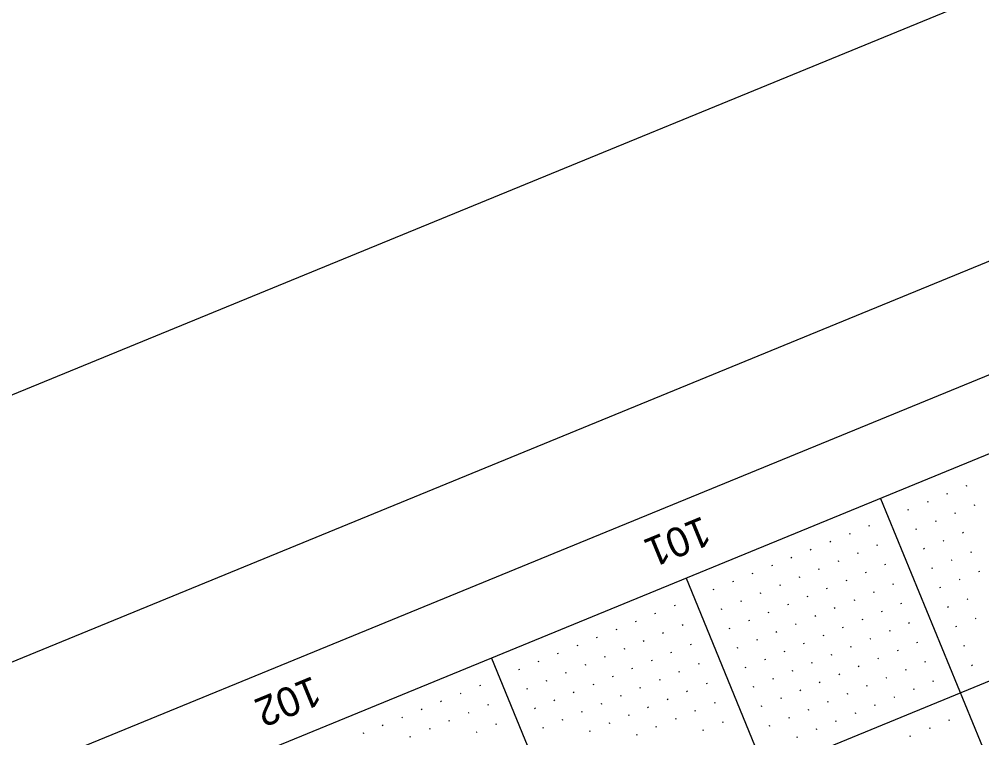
# Model space of a CAD drawing. Extents: x 2148770 to 2150891, y 142633 to 144465.
# Drawn here: x 2149281.6 to 2149510.3, y 143871.3 to 144042.2 of the extents above; entities that cross this region are included whole.
import ezdxf

# ---------------------------------------------------------------- set-up
doc = ezdxf.new("R2010")
doc.units = 0
for name, color, linetype in [('SHT_Plan_Profile_Sheet_Sta_Txt', 7, 'Continuous'), ('SHT_Plot_Shape_Full', 7, 'Continuous'), ('SHT_Plot_Shape_Half', 7, 'Continuous'), ('SHT_Profile_Grid_Major', 7, 'Continuous'), ('SHT_Profile_Grid_Minor', 7, 'Continuous'), ('SHT_Sheet_Border', 7, 'Continuous')]:
    doc.layers.add(name, color=color, linetype=linetype)

msp = doc.modelspace()

# ---------------------------------------------------------------- linework, layer by layer
at = {"layer": 'SHT_Plot_Shape_Full'}
msp.add_lwpolyline([(2150890.55, 143316.95), (2149225.42, 142633.31), (2148769.66, 143743.39), (2150434.78, 144427.04)], close=True, dxfattribs=at)
at = {"layer": 'SHT_Plot_Shape_Half'}
msp.add_lwpolyline([(2150799.14, 143324.02), (2149226.52, 142678.36), (2148808.74, 143695.93), (2150381.36, 144341.59)], close=True, dxfattribs=at)
at = {"layer": 'SHT_Profile_Grid_Major'}
for p, q in [((2150326.3, 144218.99), (2148869.31, 143620.81)), ((2149486.31, 143928.17), (2149676.21, 143465.64)), ((2149440.05, 143909.18), (2149629.95, 143446.65)), ((2149393.8, 143890.19), (2149583.7, 143427.66))]:
    msp.add_line(p, q, dxfattribs=at)
at = {"layer": 'SHT_Profile_Grid_Minor'}
for p, q in [((2149506.82, 143931.19), (2149506.59, 143931.1)), ((2149502.2, 143929.29), (2149501.97, 143929.2)), ((2149497.57, 143927.39), (2149497.34, 143927.3)), ((2149508.72, 143926.57), (2149508.49, 143926.47)), ((2149492.95, 143925.49), (2149492.72, 143925.4)), ((2149504.1, 143924.67), (2149503.87, 143924.57)), ((2149499.47, 143922.77), (2149499.24, 143922.67)), ((2149479.07, 143919.8), (2149478.84, 143919.7)), ((2149483.7, 143921.7), (2149483.46, 143921.6)), ((2149494.85, 143920.87), (2149494.61, 143920.77)), ((2149506, 143920.04), (2149505.76, 143919.95)), ((2149474.45, 143917.9), (2149474.21, 143917.8)), ((2149501.37, 143918.14), (2149501.14, 143918.05)), ((2149469.82, 143916), (2149469.59, 143915.9)), ((2149480.97, 143915.17), (2149480.74, 143915.08)), ((2149485.6, 143917.07), (2149485.36, 143916.98)), ((2149496.75, 143916.24), (2149496.51, 143916.15)), ((2149507.89, 143915.42), (2149507.66, 143915.32)), ((2149465.19, 143914.1), (2149464.96, 143914)), ((2149476.34, 143913.27), (2149476.11, 143913.18)), ((2149503.27, 143913.52), (2149503.04, 143913.42)), ((2149460.57, 143912.2), (2149460.34, 143912.11)), ((2149471.72, 143911.37), (2149471.49, 143911.28)), ((2149482.87, 143910.55), (2149482.64, 143910.45)), ((2149487.49, 143912.44), (2149487.26, 143912.35)), ((2149498.64, 143911.62), (2149498.41, 143911.52)), ((2149509.79, 143910.79), (2149509.56, 143910.7)), ((2149451.32, 143908.4), (2149451.09, 143908.31)), ((2149455.94, 143910.3), (2149455.71, 143910.21)), ((2149467.09, 143909.47), (2149466.86, 143909.38)), ((2149478.24, 143908.65), (2149478.01, 143908.55)), ((2149505.17, 143908.89), (2149504.94, 143908.8)), ((2149446.69, 143906.5), (2149446.46, 143906.41)), ((2149462.47, 143907.58), (2149462.24, 143907.48)), ((2149473.62, 143906.75), (2149473.39, 143906.65)), ((2149484.77, 143905.92), (2149484.54, 143905.83)), ((2149489.39, 143907.82), (2149489.16, 143907.72)), ((2149500.54, 143906.99), (2149500.31, 143906.9)), ((2149453.22, 143903.78), (2149452.99, 143903.68)), ((2149457.84, 143905.68), (2149457.61, 143905.58)), ((2149468.99, 143904.85), (2149468.76, 143904.75)), ((2149480.14, 143904.02), (2149479.91, 143903.93)), ((2149507.07, 143904.27), (2149506.84, 143904.17)), ((2149437.44, 143902.71), (2149437.21, 143902.61)), ((2149448.59, 143901.88), (2149448.36, 143901.78)), ((2149464.37, 143902.95), (2149464.14, 143902.85)), ((2149475.52, 143902.12), (2149475.29, 143902.03)), ((2149486.67, 143901.3), (2149486.44, 143901.2)), ((2149491.29, 143903.19), (2149491.06, 143903.1)), ((2149502.44, 143902.37), (2149502.21, 143902.27)), ((2149432.82, 143900.81), (2149432.59, 143900.71)), ((2149455.12, 143899.15), (2149454.89, 143899.06)), ((2149459.74, 143901.05), (2149459.51, 143900.96)), ((2149470.89, 143900.22), (2149470.66, 143900.13)), ((2149482.04, 143899.4), (2149481.81, 143899.3)), ((2149508.97, 143899.64), (2149508.74, 143899.55)), ((2149423.57, 143897.01), (2149423.34, 143896.91)), ((2149428.19, 143898.91), (2149427.96, 143898.81)), ((2149439.34, 143898.08), (2149439.11, 143897.99)), ((2149450.49, 143897.25), (2149450.26, 143897.16)), ((2149466.27, 143898.32), (2149466.04, 143898.23)), ((2149477.42, 143897.5), (2149477.18, 143897.4)), ((2149493.19, 143898.57), (2149492.96, 143898.47)), ((2149504.34, 143897.74), (2149504.11, 143897.65)), ((2149418.94, 143895.11), (2149418.71, 143895.01)), ((2149434.72, 143896.18), (2149434.49, 143896.09)), ((2149457.02, 143894.53), (2149456.78, 143894.43)), ((2149461.64, 143896.43), (2149461.41, 143896.33)), ((2149472.79, 143895.6), (2149472.56, 143895.5)), ((2149483.94, 143894.77), (2149483.71, 143894.68)), ((2149488.57, 143896.67), (2149488.33, 143896.57)), ((2149414.32, 143893.21), (2149414.08, 143893.12)), ((2149425.47, 143892.38), (2149425.23, 143892.29)), ((2149430.09, 143894.28), (2149429.86, 143894.19)), ((2149441.24, 143893.45), (2149441.01, 143893.36)), ((2149452.39, 143892.63), (2149452.16, 143892.53)), ((2149468.17, 143893.7), (2149467.93, 143893.6)), ((2149479.32, 143892.87), (2149479.08, 143892.78)), ((2149495.09, 143893.94), (2149494.86, 143893.85)), ((2149506.24, 143893.12), (2149506.01, 143893.02)), ((2149409.69, 143891.31), (2149409.46, 143891.22)), ((2149420.84, 143890.48), (2149420.61, 143890.39)), ((2149436.62, 143891.56), (2149436.38, 143891.46)), ((2149458.91, 143889.9), (2149458.68, 143889.81)), ((2149463.54, 143891.8), (2149463.31, 143891.71)), ((2149474.69, 143890.97), (2149474.46, 143890.88)), ((2149485.84, 143890.15), (2149485.61, 143890.05)), ((2149490.46, 143892.04), (2149490.23, 143891.95)), ((2149405.07, 143889.41), (2149404.83, 143889.32)), ((2149416.22, 143888.59), (2149415.98, 143888.49)), ((2149427.36, 143887.76), (2149427.13, 143887.66)), ((2149431.99, 143889.66), (2149431.76, 143889.56)), ((2149443.14, 143888.83), (2149442.91, 143888.73)), ((2149454.29, 143888), (2149454.06, 143887.91)), ((2149470.06, 143889.07), (2149469.83, 143888.98)), ((2149481.21, 143888.25), (2149480.98, 143888.15)), ((2149496.99, 143889.32), (2149496.76, 143889.22)), ((2149508.14, 143888.49), (2149507.91, 143888.4)), ((2149400.44, 143887.51), (2149400.21, 143887.42)), ((2149411.59, 143886.69), (2149411.36, 143886.59)), ((2149422.74, 143885.86), (2149422.51, 143885.76)), ((2149438.51, 143886.93), (2149438.28, 143886.84)), ((2149460.81, 143885.28), (2149460.58, 143885.18)), ((2149465.44, 143887.17), (2149465.21, 143887.08)), ((2149476.59, 143886.35), (2149476.36, 143886.25)), ((2149487.74, 143885.52), (2149487.51, 143885.43)), ((2149492.36, 143887.42), (2149492.13, 143887.32)), ((2149391.19, 143883.72), (2149390.96, 143883.62)), ((2149406.96, 143884.79), (2149406.73, 143884.69)), ((2149418.11, 143883.96), (2149417.88, 143883.86)), ((2149429.26, 143883.13), (2149429.03, 143883.04)), ((2149433.89, 143885.03), (2149433.66, 143884.94)), ((2149445.04, 143884.2), (2149444.81, 143884.11)), ((2149456.19, 143883.38), (2149455.96, 143883.28)), ((2149471.96, 143884.45), (2149471.73, 143884.35)), ((2149483.11, 143883.62), (2149482.88, 143883.53)), ((2149498.89, 143884.69), (2149498.66, 143884.6)), ((2149386.56, 143881.82), (2149386.33, 143881.72)), ((2149402.34, 143882.89), (2149402.11, 143882.79)), ((2149413.49, 143882.06), (2149413.26, 143881.97)), ((2149424.64, 143881.23), (2149424.41, 143881.14)), ((2149440.41, 143882.31), (2149440.18, 143882.21)), ((2149467.34, 143882.55), (2149467.11, 143882.45)), ((2149478.49, 143881.72), (2149478.26, 143881.63)), ((2149489.64, 143880.89), (2149489.41, 143880.8)), ((2149494.26, 143882.79), (2149494.03, 143882.7)), ((2149381.94, 143879.92), (2149381.71, 143879.82)), ((2149393.09, 143879.09), (2149392.86, 143879)), ((2149408.86, 143880.16), (2149408.63, 143880.07)), ((2149420.01, 143879.33), (2149419.78, 143879.24)), ((2149431.16, 143878.51), (2149430.93, 143878.41)), ((2149435.79, 143880.41), (2149435.56, 143880.31)), ((2149446.94, 143879.58), (2149446.71, 143879.48)), ((2149458.09, 143878.75), (2149457.86, 143878.66)), ((2149462.71, 143880.65), (2149462.48, 143880.56)), ((2149473.86, 143879.82), (2149473.63, 143879.73)), ((2149485.01, 143879), (2149484.78, 143878.9)), ((2149372.69, 143876.12), (2149372.46, 143876.02)), ((2149377.31, 143878.02), (2149377.08, 143877.92)), ((2149388.46, 143877.19), (2149388.23, 143877.1)), ((2149404.24, 143878.26), (2149404.01, 143878.17)), ((2149415.39, 143877.44), (2149415.16, 143877.34)), ((2149426.54, 143876.61), (2149426.31, 143876.51)), ((2149442.31, 143877.68), (2149442.08, 143877.58)), ((2149469.24, 143877.92), (2149469.01, 143877.83)), ((2149480.39, 143877.1), (2149480.16, 143877)), ((2149368.06, 143874.22), (2149367.83, 143874.13)), ((2149383.84, 143875.29), (2149383.61, 143875.2)), ((2149394.99, 143874.46), (2149394.76, 143874.37)), ((2149410.76, 143875.54), (2149410.53, 143875.44)), ((2149421.91, 143874.71), (2149421.68, 143874.61)), ((2149433.06, 143873.88), (2149432.83, 143873.79)), ((2149437.69, 143875.78), (2149437.46, 143875.69)), ((2149448.84, 143874.95), (2149448.61, 143874.86)), ((2149459.99, 143874.13), (2149459.76, 143874.03)), ((2149464.61, 143876.03), (2149464.38, 143875.93)), ((2149475.76, 143875.2), (2149475.53, 143875.1)), ((2149502.69, 143875.44), (2149502.46, 143875.35)), ((2149363.44, 143872.32), (2149363.21, 143872.23)), ((2149379.21, 143873.39), (2149378.98, 143873.3)), ((2149390.36, 143872.57), (2149390.13, 143872.47)), ((2149406.14, 143873.64), (2149405.91, 143873.54)), ((2149417.29, 143872.81), (2149417.06, 143872.72)), ((2149428.44, 143871.98), (2149428.21, 143871.89)), ((2149444.21, 143873.05), (2149443.98, 143872.96)), ((2149471.14, 143873.3), (2149470.9, 143873.2)), ((2149493.44, 143871.64), (2149493.2, 143871.55)), ((2149498.06, 143873.54), (2149497.83, 143873.45)), ((2149374.59, 143871.49), (2149374.36, 143871.4)), ((2149466.51, 143871.4), (2149466.28, 143871.3))]:
    msp.add_line(p, q, dxfattribs=at)
at = {"layer": 'SHT_Sheet_Border'}
msp.add_line((2150307.31, 144265.25), (2149093.15, 143766.76), dxfattribs=at)
msp.add_lwpolyline([(2150699.45, 143310.11), (2149242.47, 142711.93), (2148843.68, 143683.25), (2150300.66, 144281.43)], close=True, dxfattribs=at)

# ---------------------------------------------------------------- texts
at = {"layer": 'SHT_Plan_Profile_Sheet_Sta_Txt'}
for s, p in [('101', (2149444.02, 143924.05)), ('102', (2149351.39, 143886.02))]:
    msp.add_text(s, height=7, rotation=202.3213, dxfattribs=at).set_placement(p)

doc.saveas('drawing.dxf')
